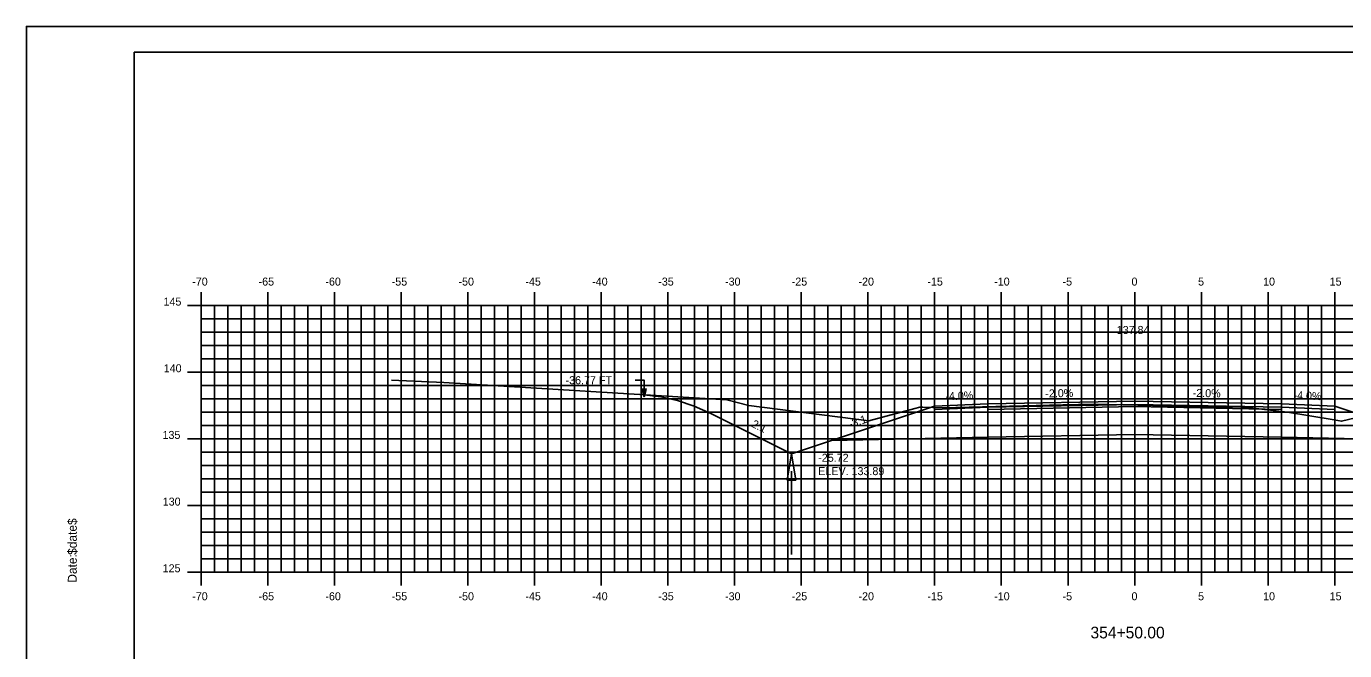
# Model space of a CAD drawing. Extents: x 1145194 to 1145364, y 608981 to 609091.
# Drawn here: x 1145194 to 1145292.9, y 609044.5 to 609091.3 of the extents above; entities that cross this region are included whole.
import ezdxf

# ---------------------------------------------------------------- set-up
doc = ezdxf.new("R2010")
doc.units = 0
for name, color, linetype in [('ANNOTATION', 7, 'Continuous'), ('BORDER', 7, 'Continuous'), ('D_Drainage_Ditch_Line', 7, 'Continuous'), ('D_Roadway_Centerline', 7, 'Continuous'), ('D_Roadway_Centerline_Text', 7, 'Continuous'), ('D_Roadway_Edge_Shoulder', 7, 'Continuous'), ('D_Roadway_Edge_TW', 7, 'Continuous'), ('D_Roadway_Pavement', 7, 'Continuous'), ('D_Roadway_SlopeLines', 7, 'Continuous'), ('D_Roadway_SubGrade', 7, 'Continuous'), ('D_Text_Standard', 7, 'Continuous'), ('H_V ANNOTATION', 7, 'Continuous'), ('MAJOR', 7, 'Continuous'), ('MINOR', 7, 'Continuous'), ('PLOT BOUNDARY', 7, 'Continuous'), ('S_Roadway_Centerline', 7, 'Continuous')]:
    doc.layers.add(name, color=color, linetype=linetype)

msp = doc.modelspace()

# ---------------------------------------------------------------- linework, layer by layer
msp.add_lwpolyline([(1145240.362, 609063.649), (1145241.612, 609063.504), (1145242.862, 609063.221), (1145244.112, 609062.802), (1145245.362, 609062.245), (1145251.407, 609059.223), (1145254.407, 609060.223), (1145262.131, 609062.797), (1145262.132, 609062.797), (1145266.132, 609062.957), (1145277.132, 609063.177), (1145288.132, 609062.957), (1145292.132, 609062.797), (1145299.855, 609060.223), (1145302.855, 609059.223), (1145310.577, 609063.083), (1145311.827, 609063.637), (1145313.077, 609064.048), (1145314.327, 609064.317), (1145315.577, 609064.443)])
at = {"layer": 'BORDER'}
msp.add_lwpolyline([(1145202.132, 608984.335), (1145362.132, 608984.335), (1145362.132, 609089.335), (1145202.132, 609089.335)], close=True, dxfattribs=at)
at = {"layer": 'D_Drainage_Ditch_Line'}
msp.add_line((1145251.407, 609057.91), (1145251.407, 609051.667), dxfattribs=at)
msp.add_lwpolyline([(1145251.735, 609057.254), (1145251.079, 609057.254), (1145251.407, 609059.223)], close=True, dxfattribs=at)
at = {"layer": 'D_Roadway_Edge_Shoulder'}
for points in [[(1145266.132, 609062.957), (1145262.132, 609062.797), (1145262.132, 609062.547), (1145266.132, 609062.707)], [(1145288.132, 609062.957), (1145292.132, 609062.797), (1145292.132, 609062.547), (1145288.132, 609062.707)]]:
    msp.add_lwpolyline(points, close=True, dxfattribs=at)
at = {"layer": 'D_Roadway_Edge_TW'}
msp.add_lwpolyline([(1145266.132, 609062.707), (1145266.132, 609062.957), (1145277.132, 609063.177), (1145288.132, 609062.957), (1145288.132, 609062.707), (1145277.132, 609062.927)], close=True, dxfattribs=at)
at = {"layer": 'D_Roadway_Pavement'}
msp.add_lwpolyline([(1145266.132, 609062.54), (1145266.132, 609062.707), (1145277.132, 609062.927), (1145288.132, 609062.707), (1145288.132, 609062.54), (1145277.132, 609062.76)], close=True, dxfattribs=at)
at = {"layer": 'D_Roadway_SlopeLines'}
for points in [[(1145251.407, 609059.223), (1145245.362, 609062.245), (1145244.112, 609062.802), (1145242.862, 609063.221), (1145241.612, 609063.504), (1145240.362, 609063.649)], [(1145254.407, 609060.223), (1145251.407, 609059.223)]]:
    msp.add_lwpolyline(points, dxfattribs=at)
at = {"layer": 'D_Roadway_SubGrade'}
for points in [[(1145266.132, 609062.54), (1145266.132, 609062.707), (1145262.132, 609062.547), (1145262.132, 609062.797), (1145262.131, 609062.797), (1145254.407, 609060.223), (1145266.132, 609060.457)], [(1145266.132, 609060.457), (1145266.132, 609062.54), (1145277.132, 609062.76), (1145288.132, 609062.54), (1145288.132, 609060.457), (1145277.132, 609060.677)], [(1145288.132, 609062.54), (1145288.132, 609062.707), (1145292.132, 609062.547), (1145292.132, 609062.797), (1145292.132, 609062.797), (1145299.855, 609060.223), (1145288.132, 609060.457)]]:
    msp.add_lwpolyline(points, close=True, dxfattribs=at)
at = {"layer": 'D_Text_Standard'}
msp.add_lwpolyline([(1145240.362, 609063.495), (1145240.362, 609064.738), (1145239.682, 609064.738)], dxfattribs=at)
msp.add_lwpolyline([(1145240.362, 609063.495), (1145240.217, 609064.077), (1145240.508, 609064.077)], close=True, dxfattribs=at)
at = {"layer": 'MAJOR'}
for p, q in [((1145207.132, 609071.337), (1145207.132, 609070.335)), ((1145212.132, 609071.337), (1145212.132, 609070.335)), ((1145217.132, 609071.337), (1145217.132, 609070.335)), ((1145222.132, 609071.337), (1145222.132, 609070.335)), ((1145227.132, 609071.337), (1145227.132, 609070.335)), ((1145232.132, 609071.337), (1145232.132, 609070.335)), ((1145237.132, 609071.337), (1145237.132, 609070.335)), ((1145242.132, 609071.337), (1145242.132, 609070.335)), ((1145247.132, 609071.337), (1145247.132, 609070.335)), ((1145252.132, 609071.337), (1145252.132, 609070.335)), ((1145257.132, 609071.337), (1145257.132, 609070.335)), ((1145262.132, 609071.337), (1145262.132, 609070.335)), ((1145267.132, 609071.337), (1145267.132, 609070.335)), ((1145272.132, 609071.337), (1145272.132, 609070.335)), ((1145277.132, 609071.337), (1145277.132, 609070.335)), ((1145282.132, 609071.337), (1145282.132, 609070.335)), ((1145287.132, 609071.337), (1145287.132, 609070.335)), ((1145292.132, 609071.337), (1145292.132, 609070.335)), ((1145206.13, 609070.335), (1145207.132, 609070.335)), ((1145207.132, 609070.335), (1145347.132, 609070.335)), ((1145207.132, 609050.335), (1145207.132, 609070.335)), ((1145207.132, 609050.335), (1145207.132, 609070.335)), ((1145207.132, 609070.335), (1145347.132, 609070.335)), ((1145212.132, 609050.335), (1145212.132, 609070.335)), ((1145217.132, 609050.335), (1145217.132, 609070.335)), ((1145222.132, 609050.335), (1145222.132, 609070.335)), ((1145227.132, 609050.335), (1145227.132, 609070.335)), ((1145232.132, 609050.335), (1145232.132, 609070.335)), ((1145237.132, 609050.335), (1145237.132, 609070.335)), ((1145242.132, 609050.335), (1145242.132, 609070.335)), ((1145247.132, 609050.335), (1145247.132, 609070.335)), ((1145252.132, 609050.335), (1145252.132, 609070.335)), ((1145257.132, 609050.335), (1145257.132, 609070.335)), ((1145262.132, 609050.335), (1145262.132, 609070.335)), ((1145267.132, 609050.335), (1145267.132, 609070.335)), ((1145272.132, 609050.335), (1145272.132, 609070.335)), ((1145277.132, 609050.335), (1145277.132, 609070.335)), ((1145282.132, 609050.335), (1145282.132, 609070.335)), ((1145287.132, 609050.335), (1145287.132, 609070.335)), ((1145292.132, 609050.335), (1145292.132, 609070.335)), ((1145206.13, 609065.335), (1145207.132, 609065.335)), ((1145207.132, 609065.335), (1145347.132, 609065.335)), ((1145206.13, 609060.335), (1145207.132, 609060.335)), ((1145207.132, 609060.335), (1145347.132, 609060.335)), ((1145206.13, 609055.335), (1145207.132, 609055.335)), ((1145207.132, 609055.335), (1145347.132, 609055.335)), ((1145206.13, 609050.335), (1145207.132, 609050.335)), ((1145207.132, 609050.335), (1145347.132, 609050.335)), ((1145207.132, 609050.335), (1145347.132, 609050.335)), ((1145207.132, 609049.333), (1145207.132, 609050.335)), ((1145212.132, 609049.333), (1145212.132, 609050.335)), ((1145217.132, 609049.333), (1145217.132, 609050.335)), ((1145222.132, 609049.333), (1145222.132, 609050.335)), ((1145227.132, 609049.333), (1145227.132, 609050.335)), ((1145232.132, 609049.333), (1145232.132, 609050.335)), ((1145237.132, 609049.333), (1145237.132, 609050.335)), ((1145242.132, 609049.333), (1145242.132, 609050.335)), ((1145247.132, 609049.333), (1145247.132, 609050.335)), ((1145252.132, 609049.333), (1145252.132, 609050.335)), ((1145257.132, 609049.333), (1145257.132, 609050.335)), ((1145262.132, 609049.333), (1145262.132, 609050.335)), ((1145267.132, 609049.333), (1145267.132, 609050.335)), ((1145272.132, 609049.333), (1145272.132, 609050.335)), ((1145277.132, 609049.333), (1145277.132, 609050.335)), ((1145282.132, 609049.333), (1145282.132, 609050.335)), ((1145287.132, 609049.333), (1145287.132, 609050.335)), ((1145292.132, 609049.333), (1145292.132, 609050.335))]:
    msp.add_line(p, q, dxfattribs=at)
at = {"layer": 'MINOR'}
for p, q in [((1145208.132, 609050.335), (1145208.132, 609070.335)), ((1145209.132, 609050.335), (1145209.132, 609070.335)), ((1145210.132, 609050.335), (1145210.132, 609070.335)), ((1145211.132, 609050.335), (1145211.132, 609070.335)), ((1145213.132, 609050.335), (1145213.132, 609070.335)), ((1145214.132, 609050.335), (1145214.132, 609070.335)), ((1145215.132, 609050.335), (1145215.132, 609070.335)), ((1145216.132, 609050.335), (1145216.132, 609070.335)), ((1145218.132, 609050.335), (1145218.132, 609070.335)), ((1145219.132, 609050.335), (1145219.132, 609070.335)), ((1145220.132, 609050.335), (1145220.132, 609070.335)), ((1145221.132, 609050.335), (1145221.132, 609070.335)), ((1145223.132, 609050.335), (1145223.132, 609070.335)), ((1145224.132, 609050.335), (1145224.132, 609070.335)), ((1145225.132, 609050.335), (1145225.132, 609070.335)), ((1145226.132, 609050.335), (1145226.132, 609070.335)), ((1145228.132, 609050.335), (1145228.132, 609070.335)), ((1145229.132, 609050.335), (1145229.132, 609070.335)), ((1145230.132, 609050.335), (1145230.132, 609070.335)), ((1145231.132, 609050.335), (1145231.132, 609070.335)), ((1145233.132, 609050.335), (1145233.132, 609070.335)), ((1145234.132, 609050.335), (1145234.132, 609070.335)), ((1145235.132, 609050.335), (1145235.132, 609070.335)), ((1145236.132, 609050.335), (1145236.132, 609070.335)), ((1145238.132, 609050.335), (1145238.132, 609070.335)), ((1145239.132, 609050.335), (1145239.132, 609070.335)), ((1145240.132, 609050.335), (1145240.132, 609070.335)), ((1145241.132, 609050.335), (1145241.132, 609070.335)), ((1145243.132, 609050.335), (1145243.132, 609070.335)), ((1145244.132, 609050.335), (1145244.132, 609070.335)), ((1145245.132, 609050.335), (1145245.132, 609070.335)), ((1145246.132, 609050.335), (1145246.132, 609070.335)), ((1145248.132, 609050.335), (1145248.132, 609070.335)), ((1145249.132, 609050.335), (1145249.132, 609070.335)), ((1145250.132, 609050.335), (1145250.132, 609070.335)), ((1145251.132, 609050.335), (1145251.132, 609070.335)), ((1145253.132, 609050.335), (1145253.132, 609070.335)), ((1145254.132, 609050.335), (1145254.132, 609070.335)), ((1145255.132, 609050.335), (1145255.132, 609070.335)), ((1145256.132, 609050.335), (1145256.132, 609070.335)), ((1145258.132, 609050.335), (1145258.132, 609070.335)), ((1145259.132, 609050.335), (1145259.132, 609070.335)), ((1145260.132, 609050.335), (1145260.132, 609070.335)), ((1145261.132, 609050.335), (1145261.132, 609070.335)), ((1145263.132, 609050.335), (1145263.132, 609070.335)), ((1145264.132, 609050.335), (1145264.132, 609070.335)), ((1145265.132, 609050.335), (1145265.132, 609070.335)), ((1145266.132, 609050.335), (1145266.132, 609070.335)), ((1145268.132, 609050.335), (1145268.132, 609070.335)), ((1145269.132, 609050.335), (1145269.132, 609070.335)), ((1145270.132, 609050.335), (1145270.132, 609070.335)), ((1145271.132, 609050.335), (1145271.132, 609070.335)), ((1145273.132, 609050.335), (1145273.132, 609070.335)), ((1145274.132, 609050.335), (1145274.132, 609070.335)), ((1145275.132, 609050.335), (1145275.132, 609070.335)), ((1145276.132, 609050.335), (1145276.132, 609070.335)), ((1145278.132, 609050.335), (1145278.132, 609070.335)), ((1145279.132, 609050.335), (1145279.132, 609070.335)), ((1145280.132, 609050.335), (1145280.132, 609070.335)), ((1145281.132, 609050.335), (1145281.132, 609070.335)), ((1145283.132, 609050.335), (1145283.132, 609070.335)), ((1145284.132, 609050.335), (1145284.132, 609070.335)), ((1145285.132, 609050.335), (1145285.132, 609070.335)), ((1145286.132, 609050.335), (1145286.132, 609070.335)), ((1145288.132, 609050.335), (1145288.132, 609070.335)), ((1145289.132, 609050.335), (1145289.132, 609070.335)), ((1145290.132, 609050.335), (1145290.132, 609070.335)), ((1145291.132, 609050.335), (1145291.132, 609070.335)), ((1145207.132, 609069.335), (1145347.132, 609069.335)), ((1145207.132, 609069.335), (1145208.134, 609069.335)), ((1145207.132, 609068.335), (1145347.132, 609068.335)), ((1145207.132, 609068.335), (1145208.134, 609068.335)), ((1145207.132, 609067.335), (1145347.132, 609067.335)), ((1145207.132, 609067.335), (1145208.134, 609067.335)), ((1145207.132, 609066.335), (1145347.132, 609066.335)), ((1145207.132, 609066.335), (1145208.134, 609066.335)), ((1145207.132, 609064.335), (1145347.132, 609064.335)), ((1145207.132, 609064.335), (1145208.134, 609064.335)), ((1145207.132, 609063.335), (1145347.132, 609063.335)), ((1145207.132, 609063.335), (1145208.134, 609063.335)), ((1145207.132, 609062.335), (1145347.132, 609062.335)), ((1145207.132, 609062.335), (1145208.134, 609062.335)), ((1145207.132, 609061.335), (1145347.132, 609061.335)), ((1145207.132, 609061.335), (1145208.134, 609061.335)), ((1145207.132, 609059.335), (1145347.132, 609059.335)), ((1145207.132, 609059.335), (1145208.134, 609059.335)), ((1145207.132, 609058.335), (1145347.132, 609058.335)), ((1145207.132, 609058.335), (1145208.134, 609058.335)), ((1145207.132, 609057.335), (1145347.132, 609057.335)), ((1145207.132, 609057.335), (1145208.134, 609057.335)), ((1145207.132, 609056.335), (1145347.132, 609056.335)), ((1145207.132, 609056.335), (1145208.134, 609056.335)), ((1145207.132, 609054.335), (1145347.132, 609054.335)), ((1145207.132, 609054.335), (1145208.134, 609054.335)), ((1145207.132, 609053.335), (1145347.132, 609053.335)), ((1145207.132, 609053.335), (1145208.134, 609053.335)), ((1145207.132, 609052.335), (1145347.132, 609052.335)), ((1145207.132, 609052.335), (1145208.134, 609052.335)), ((1145207.132, 609051.335), (1145347.132, 609051.335)), ((1145207.132, 609051.335), (1145208.134, 609051.335))]:
    msp.add_line(p, q, dxfattribs=at)
at = {"layer": 'PLOT BOUNDARY'}
msp.add_lwpolyline([(1145194.039, 608981.276), (1145364.039, 608981.276), (1145364.039, 609091.276), (1145194.039, 609091.276)], close=True, dxfattribs=at)
at = {"layer": 'S_Roadway_Centerline'}
msp.add_lwpolyline([(1145221.402, 609064.735), (1145225.329, 609064.575), (1145246.561, 609063.268), (1145248.193, 609062.854), (1145257.196, 609061.684), (1145260.651, 609062.618), (1145261.032, 609062.705), (1145261.259, 609062.722), (1145262.732, 609062.678), (1145271.744, 609062.884), (1145274.056, 609062.93), (1145282.857, 609062.744), (1145285.086, 609062.712), (1145286.013, 609062.635), (1145288.576, 609062.35), (1145292.097, 609061.764), (1145292.643, 609061.658), (1145296.634, 609062.619), (1145300.948, 609063.802), (1145310.099, 609064.202), (1145329.411, 609065.052)], dxfattribs=at)

# ---------------------------------------------------------------- texts
at = {"layer": 'ANNOTATION'}
for s, rotation, p in [('-2.0%', 1.14576, (1145270.435, 609063.443)), ('-2.0%', 358.85424, (1145281.475, 609063.49)), ('-4.0%', 2.29061, (1145262.948, 609063.231)), ('-4.0%', 357.70939, (1145289.028, 609063.322)), ('-3:1', 18.43482, (1145255.786, 609061.136)), ('2:1', 333.43495, (1145248.352, 609061.268))]:
    msp.add_text(s, height=0.6, rotation=rotation, dxfattribs=at).set_placement(p)
at = {"layer": 'BORDER'}
for s, p in [('$date$', (1145197.817, 609051.64)), ('Date:', (1145197.817, 609049.552))]:
    msp.add_text(s, height=0.6696, rotation=90, dxfattribs=at).set_placement(p)
at = {"layer": 'D_Roadway_Centerline'}
for s, p in [('C', (1145277.127, 609063.177)), ('L', (1145277.132, 609063.17))]:
    msp.add_text(s, height=0.0146, dxfattribs=at).set_placement(p)
at = {"layer": 'D_Roadway_Centerline_Text'}
msp.add_text('137.84', height=0.6, dxfattribs=at).set_placement((1145275.783, 609068.209))
at = {"layer": 'D_Text_Standard'}
for s, p in [('-36.77 FT', (1145234.463, 609064.438)), ('-25.72', (1145253.407, 609058.623)), ('ELEV. 133.89', (1145253.407, 609057.621))]:
    msp.add_text(s, height=0.6, dxfattribs=at).set_placement(p)
at = {"layer": 'H_V ANNOTATION'}
for s, height, p in [('-70', 0.6, (1145206.474, 609071.835)), ('-65', 0.6, (1145211.45, 609071.835)), ('-60', 0.6, (1145216.458, 609071.835)), ('-55', 0.6, (1145221.428, 609071.835)), ('-50', 0.6, (1145226.436, 609071.835)), ('-45', 0.6, (1145231.45, 609071.835)), ('-40', 0.6, (1145236.458, 609071.835)), ('-35', 0.6, (1145241.412, 609071.835)), ('-30', 0.6, (1145246.42, 609071.835)), ('-25', 0.6, (1145251.417, 609071.835)), ('-20', 0.6, (1145256.425, 609071.835)), ('-15', 0.6, (1145261.589, 609071.835)), ('-10', 0.6, (1145266.597, 609071.835)), ('-5', 0.6, (1145271.723, 609071.835)), ('0', 0.6, (1145276.891, 609071.835)), ('5', 0.6, (1145281.883, 609071.835)), ('10', 0.6, (1145286.757, 609071.835)), ('15', 0.6, (1145291.749, 609071.835)), ('145', 0.6, (1145204.321, 609070.335)), ('140', 0.6, (1145204.337, 609065.335)), ('135', 0.6, (1145204.246, 609060.335)), ('130', 0.6, (1145204.262, 609055.335)), ('125', 0.6, (1145204.256, 609050.335)), ('-70', 0.6, (1145206.474, 609048.235)), ('-65', 0.6, (1145211.45, 609048.235)), ('-60', 0.6, (1145216.458, 609048.235)), ('-55', 0.6, (1145221.428, 609048.235)), ('-50', 0.6, (1145226.436, 609048.235)), ('-45', 0.6, (1145231.45, 609048.235)), ('-40', 0.6, (1145236.458, 609048.235)), ('-35', 0.6, (1145241.412, 609048.235)), ('-30', 0.6, (1145246.42, 609048.235)), ('-25', 0.6, (1145251.417, 609048.235)), ('-20', 0.6, (1145256.425, 609048.235)), ('-15', 0.6, (1145261.589, 609048.235)), ('-10', 0.6, (1145266.597, 609048.235)), ('-5', 0.6, (1145271.723, 609048.235)), ('0', 0.6, (1145276.891, 609048.235)), ('5', 0.6, (1145281.883, 609048.235)), ('10', 0.6, (1145286.757, 609048.235)), ('15', 0.6, (1145291.749, 609048.235)), ('354+50.00', 0.875, (1145273.816, 609045.378))]:
    msp.add_text(s, height=height, dxfattribs=at).set_placement(p)
at = {"layer": 'MAJOR'}
msp.add_text('-', height=0.006, dxfattribs=at).set_placement((1145207.128, 609050.335))
at = {"layer": 'S_Roadway_Centerline'}
for s, p in [('L', (1145274.048, 609062.922)), ('C', (1145274.051, 609062.93))]:
    msp.add_text(s, height=0.0146, dxfattribs=at).set_placement(p)

doc.saveas('drawing.dxf')
